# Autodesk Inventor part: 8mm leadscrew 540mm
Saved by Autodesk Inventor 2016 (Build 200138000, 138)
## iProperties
Created: 2015-11
Part Number: 8mm leadscrew 540mm
Material: Generic
Document SubType Name: Modeling
Designer: John
Density: 1 g/cm^3
Appearance: Default
Author: John
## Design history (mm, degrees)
feature "SOLID1"
body "Solid1"
